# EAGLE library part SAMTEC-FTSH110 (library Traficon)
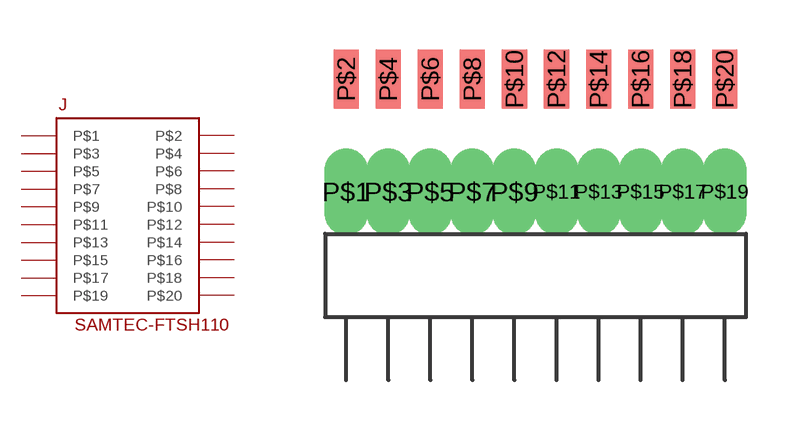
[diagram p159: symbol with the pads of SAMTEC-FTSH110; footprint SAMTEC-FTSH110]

Designator prefix J

## SAMTEC-FTSH110  [SAMTEC-FTSH110]
P$1  P$1
P$2  P$2
P$3  P$3
P$4  P$4
P$5  P$5
P$6  P$6
P$7  P$7
P$8  P$8
P$9  P$9
P$10  P$10
P$11  P$11
P$12  P$12
P$13  P$13
P$14  P$14
P$15  P$15
P$16  P$16
P$17  P$17
P$18  P$18
P$19  P$19
P$20  P$20

## Footprint SAMTEC-FTSH110 (pad centres in mm)
drill 0.8 pad 1.016 long: P$1 -5.715,-2.16; P$3 -4.445,-2.16; P$5 -3.175,-2.16; P$7 -1.905,-2.16; P$9 -0.635,-2.16; P$11 0.635,-2.16; P$13 1.905,-2.16; P$15 3.175,-2.16; P$17 4.445,-2.16; P$19 5.715,-2.16
smd 0.76 x 1.78: P$2 -5.715,1.25; P$4 -4.445,1.25; P$6 -3.175,1.25; P$8 -1.905,1.25; P$10 -0.635,1.25; P$12 0.635,1.25; P$14 1.905,1.25; P$16 3.175,1.25; P$18 4.445,1.25; P$20 5.715,1.25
